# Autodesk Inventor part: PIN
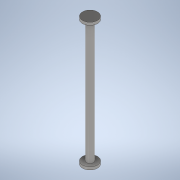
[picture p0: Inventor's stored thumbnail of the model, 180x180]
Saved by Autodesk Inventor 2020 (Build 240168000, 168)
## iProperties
Created: 2023-04
Part Number: PIN
Material: Generic
Document SubType Name: Modeling
Designer: gzb
Density: 1 g/cm^3
Appearance: Steel - Polished
Author: gzb
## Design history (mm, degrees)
sketch "Sketch1"
  geometry: L1 (0, 0)-(0, 95); L2 (-2.5, 0)-(-2.5, 92); L3 (-2.5, 92)-(-5.5, 92); L4 (-5.5, 92)-(-5.5, 94); L5 (-5.5, 94)-(0, 94); L6 (0, 95)-(0, 94); L7 (-2.5, 0)-(0, 0); 1 further point
  constraints: 14 end point, 4 perpendicular, 2 vertical, 1 horizontal, 1 horizontal alignment
  dimensions: "d1" = 92 distance of L2.start L2.end; "d2" = 2 distance between parallel lines of L3 L5; "d3" = 2.5 distance between parallel lines of L1 L2; "d4" = 5.5 distance between parallel lines of L1 L4
revolve "Revolution1" sketch "Sketch1" stored, may be unused: angle "d5" = 90 deg
workplane "Work Plane1"
mirror "Mirror1"
body "Solid1"
